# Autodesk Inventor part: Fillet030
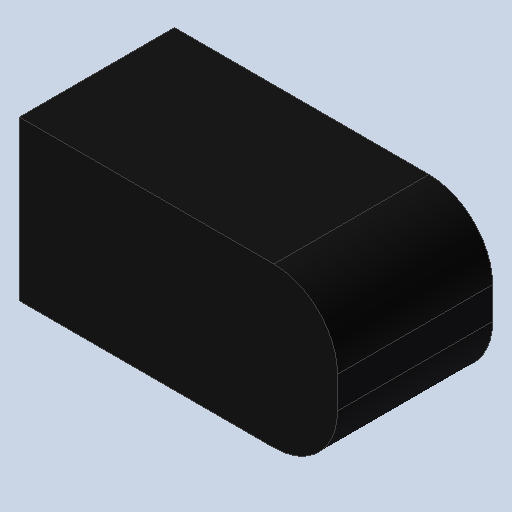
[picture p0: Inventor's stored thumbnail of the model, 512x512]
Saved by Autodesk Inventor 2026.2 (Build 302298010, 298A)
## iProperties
Created: 2026-10
Part Number: Fillet030
Material: Générique
Document SubType Name: Modeling
Designer: mel
Density: 1 g/cm^3
Appearance: Par défaut
Author: mel
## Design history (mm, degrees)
feature "Base1"
node "Solide1"
